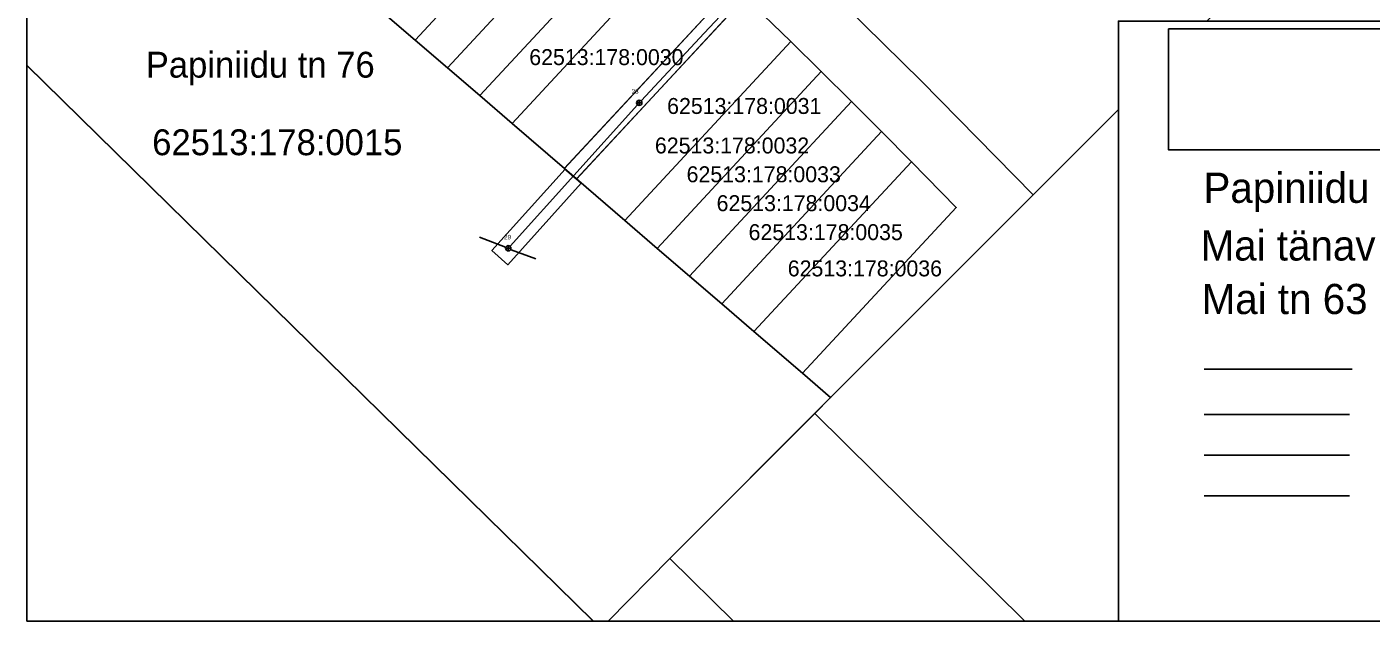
# Model space of a CAD drawing. Extents: x 531722 to 532110, y 6469397 to 6469678.
# Drawn here: x 531722.3 to 531975.1, y 6469396.9 to 6469508.7 of the extents above; entities that cross this region are included whole.
import ezdxf

# ---------------------------------------------------------------- set-up
doc = ezdxf.new("R2010")
doc.units = 0
for name, color, linetype in [('ABIJOONIS', 7, 'Continuous'), ('Default', 7, 'Continuous'), ('IKÕ alad', 7, 'Continuous'), ('KAEVUNR_SKKAEV', 7, 'Continuous'), ('PIIR', 7, 'Continuous'), ('PIIRIMLEITUD', 7, 'Continuous'), ('SKKAEV', 7, 'Continuous'), ('SKTRASS', 7, 'Continuous'), ('VORMISTUS', 7, 'Continuous')]:
    doc.layers.add(name, color=color, linetype=linetype)

msp = doc.modelspace()

# ---------------------------------------------------------------- linework, layer by layer
at = {"layer": 'IKÕ alad'}
msp.add_lwpolyline([(531857.33, 6469514.25), (531825.63, 6469480.06), (531823.36, 6469482.02), (531855.16, 6469516.33)], dxfattribs=at)
msp.add_lwpolyline([(531826.55, 6469479.3), (531812.73, 6469463.94), (531809.76, 6469466.62), (531823.52, 6469481.91)], close=True, dxfattribs=at)
at = {"layer": 'PIIR'}
for p, q in [((531943.67, 6469444.28), (531971.5, 6469444.28)), ((531943.67, 6469435.75), (531971.04, 6469435.75)), ((531943.67, 6469428.12), (531971.04, 6469428.12)), ((531943.67, 6469420.48), (531971.04, 6469420.48))]:
    msp.add_line(p, q, dxfattribs=at)
at = {"layer": 'PIIRIMLEITUD'}
for points in [[(531722.31, 6469569), (531723.77, 6469567.74), (531764.98, 6469532.29), (531771.05, 6469527.07), (531777.12, 6469521.84), (531789.25, 6469511.4), (531795.32, 6469506.18), (531801.39, 6469500.96), (531807.46, 6469495.74), (531813.53, 6469490.51), (531823.39, 6469482.03), (531825.66, 6469480.07), (531834.75, 6469472.24), (531840.82, 6469467.02), (531846.89, 6469461.8), (531852.96, 6469456.57), (531859.03, 6469451.36), (531868.13, 6469443.53), (531873.44, 6469438.96), (531843.23, 6469408.7), (531831.64, 6469396.91)], [(531927.55, 6469493.15), (531911.54, 6469477.11), (531890.48, 6469498.54), (531869.08, 6469519.62), (531868.96, 6469525.97), (531878.09, 6469535.46), (531892, 6469548.07), (531908.6, 6469558.08), (531913.6, 6469547.88), (531950.63, 6469516.26), (531944.16, 6469509.78)], [(531869.08, 6469519.62), (531890.48, 6469498.54), (531911.54, 6469477.11), (531873.44, 6469438.96), (531868.13, 6469443.53), (531897.06, 6469474.73), (531888.66, 6469483.32), (531883.03, 6469489.01), (531877.37, 6469494.67), (531871.68, 6469500.3), (531865.97, 6469505.91), (531857.35, 6469514.26), (531825.66, 6469480.07), (531823.39, 6469482.03), (531855.18, 6469516.34)], [(531828.83, 6469396.91), (531722.31, 6469501.48)], [(531722.31, 6469501.42), (531828.78, 6469396.91)], [(531909.94, 6469396.91), (531870.45, 6469435.97), (531873.44, 6469438.96), (531911.54, 6469477.11), (531927.55, 6469493.15)], [(531855.15, 6469396.91), (531843.23, 6469408.7), (531870.45, 6469435.97), (531909.94, 6469396.91)]]:
    msp.add_lwpolyline(points, dxfattribs=at)
for points in [[(531822.27, 6469547.02), (531828.18, 6469541.63), (531795.32, 6469506.18), (531789.25, 6469511.4)], [(531828.18, 6469541.63), (531834.07, 6469536.22), (531801.39, 6469500.96), (531795.32, 6469506.18)], [(531834.07, 6469536.22), (531839.93, 6469530.77), (531807.46, 6469495.74), (531801.39, 6469500.96)], [(531839.93, 6469530.77), (531845.76, 6469525.29), (531813.53, 6469490.51), (531807.46, 6469495.74)], [(531845.76, 6469525.29), (531855.18, 6469516.34), (531823.39, 6469482.03), (531813.53, 6469490.51)], [(531857.35, 6469514.26), (531865.97, 6469505.91), (531834.75, 6469472.24), (531825.66, 6469480.07)], [(531865.97, 6469505.91), (531871.68, 6469500.3), (531840.82, 6469467.02), (531834.75, 6469472.24)], [(531871.68, 6469500.3), (531877.37, 6469494.67), (531846.89, 6469461.8), (531840.82, 6469467.02)], [(531877.37, 6469494.67), (531883.03, 6469489.01), (531852.96, 6469456.57), (531846.89, 6469461.8)], [(531883.03, 6469489.01), (531888.66, 6469483.32), (531859.03, 6469451.36), (531852.96, 6469456.57)], [(531888.66, 6469483.32), (531897.06, 6469474.73), (531868.13, 6469443.53), (531859.03, 6469451.36)]]:
    msp.add_lwpolyline(points, close=True, dxfattribs=at)
at = {"layer": 'SKKAEV'}
for p, q in [((531837.96, 6469494.39), (531836.96, 6469494.39)), ((531837.46, 6469494.91), (531837.46, 6469493.89)), ((531812.82, 6469467.55), (531812.82, 6469466.53)), ((531813.33, 6469467.03), (531812.33, 6469467.03))]:
    msp.add_line(p, q, dxfattribs=at)
for centre in [(531837.46, 6469494.4), (531812.82, 6469467.04)]:
    msp.add_circle(centre, 0.5, dxfattribs=at)
at = {"layer": 'SKTRASS'}
for points in [[(531837.8, 6469494.77), (531849.68, 6469507.5), (531852.65, 6469510.67), (531860.82, 6469519.43)], [(531813.16, 6469467.41), (531837.12, 6469494.03)], [(531807.42, 6469469.14), (531812.32, 6469467.25)], [(531813.37, 6469466.77), (531818, 6469465.06)]]:
    msp.add_lwpolyline(points, dxfattribs=at)
at = {"layer": 'VORMISTUS'}
msp.add_lwpolyline([(531722.31, 6469396.91), (531927.55, 6469396.91), (531927.55, 6469509.78), (532109.74, 6469509.78), (532109.74, 6469678.27), (531722.31, 6469678.27), (531722.31, 6469396.91)], dxfattribs=at)
for points in [[(532109.74, 6469396.91), (531722.31, 6469396.91), (531722.31, 6469678.27), (532109.74, 6469678.27)], [(531936.95, 6469508.32), (531978.8, 6469508.32), (531978.8, 6469485.56), (531936.95, 6469485.56)]]:
    msp.add_lwpolyline(points, close=True, dxfattribs=at)

# ---------------------------------------------------------------- texts
at = {"layer": 'ABIJOONIS'}
for s, p in [('62513:178:0030', (531816.77, 6469501.49)), ('62513:178:0031', (531842.7, 6469492.3)), ('62513:178:0032', (531840.4, 6469484.87)), ('62513:178:0033', (531846.36, 6469479.45)), ('62513:178:0034', (531852, 6469474.02)), ('62513:178:0035', (531858.01, 6469468.57)), ('62513:178:0036', (531865.38, 6469461.75))]:
    msp.add_text(s, height=3, dxfattribs=at).set_placement(p)
at = {"layer": 'Default'}
for s, p in [('Papiniidu tn 76', (531744.66, 6469499.13)), ('62513:178:0015', (531745.87, 6469484.54))]:
    msp.add_text(s, height=4.8664, dxfattribs=at).set_placement(p)
for s, height, p in [('Papiniidu tn 76', 5.6737, (531943.55, 6469475.58)), ('Mai tänav T1', 5.6737, (531943.01, 6469464.73)), ('Mai tn 63', 5.674, (531943.2, 6469454.66))]:
    msp.add_text(s, height=height, rotation=360, dxfattribs=at).set_placement(p)
at = {"layer": 'KAEVUNR_SKKAEV'}
for s, p in [('28', (531836.02, 6469496.09)), ('29', (531812.04, 6469468.71))]:
    msp.add_text(s, height=0.85, rotation=0.0017, dxfattribs=at).set_placement(p)

doc.saveas('drawing.dxf')
